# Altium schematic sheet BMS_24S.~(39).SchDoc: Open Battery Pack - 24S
size A3; Date: 26/03/2019; Author: Morgane Vallée - Samuel Lesueur; Revision: 1.0; SheetNumber: 3; SheetTotal: 5
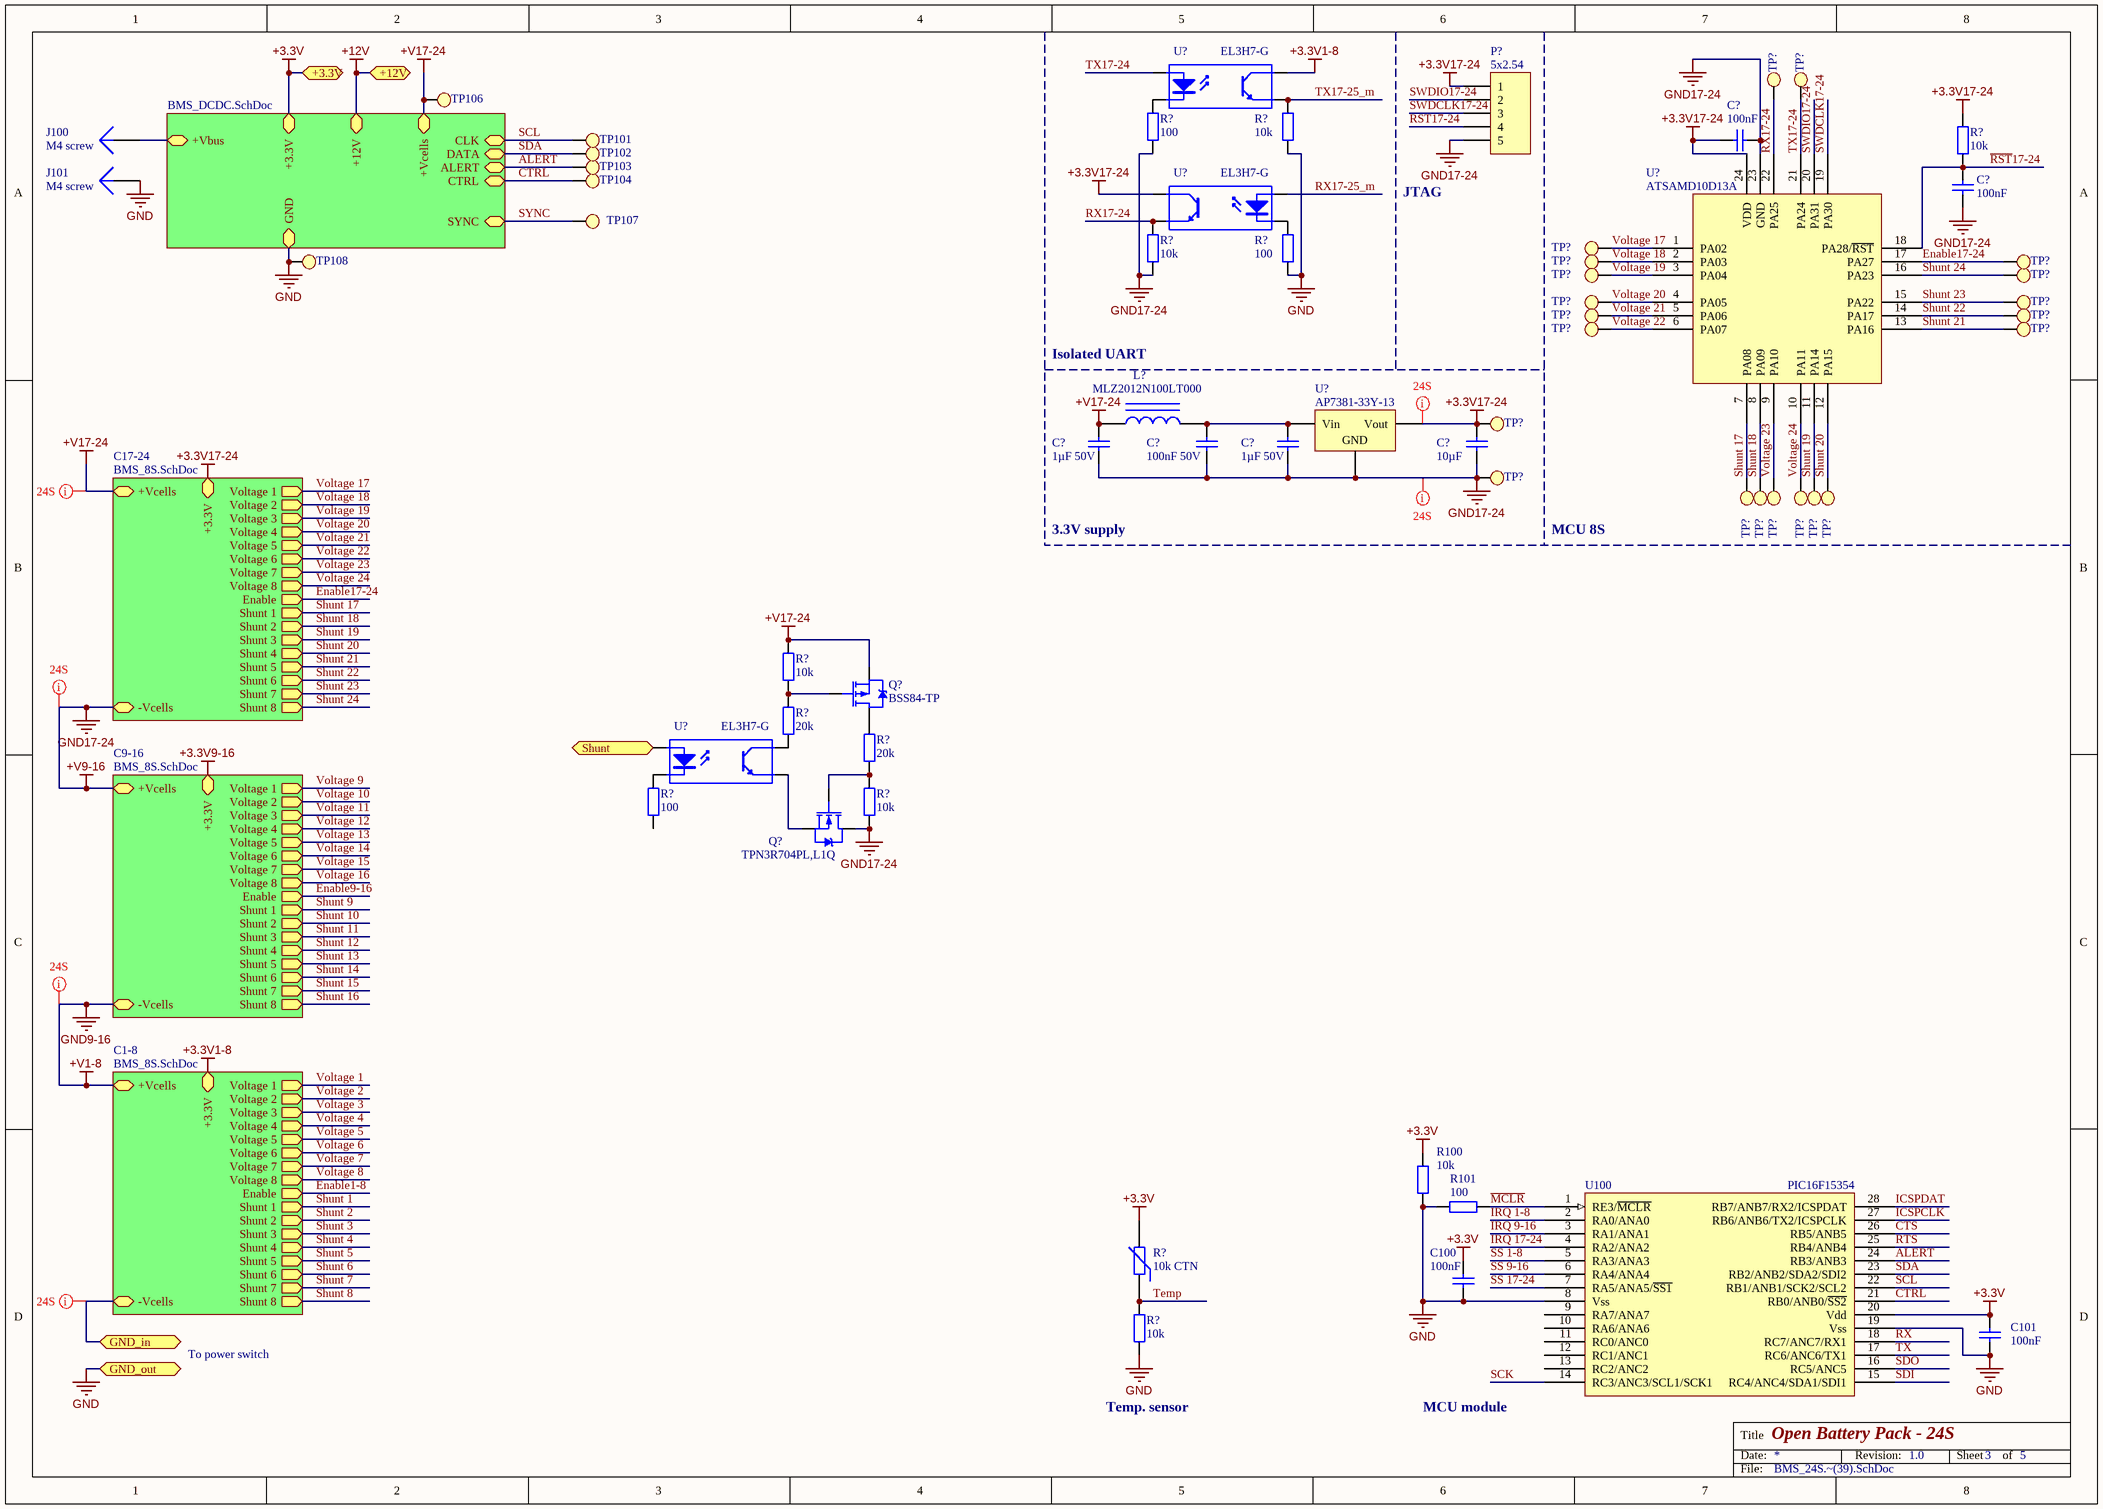
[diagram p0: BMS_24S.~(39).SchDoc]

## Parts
(Parts that share a designator on the sheet are numbered #1, #2 ... from top to bottom, then left to right.)
C100  100nF  [C0603]
C101  100nF  [C0603]
C?#1  100nF  [C0603]
C?#2  100nF  [C0603]
C?#3  1µF 50V  [C0805]
C?#4  100nF 50V  [C0603]
C?#5  1µF 50V  [C0805]
C?#6  10µF  [C0603]
J100  M4 screw  [HOLE_4]
J101  M4 screw  [HOLE_4]
L?  MLZ2012N100LT000  [FER 0805/2012]
P?  5x2.54  [HDR1X5]
Q?#1  BSS84-TP  [DIODES SOT-23-3]
Q?#2  TPN3R704PL,L1Q  [DIODES SOT-23-3]
R100  10k  [R0603]
R101  100  [R0603]
R?#1  10k  [R0603]
R?#2  100  [R0603]
R?#3  10k  [R0603]
R?#4  100  [R0603]
R?#5  10k  [R0603]
R?#6  10k  [R0603]
R?#7  20k  [R0603]
R?#8  20k  [R0603]
R?#9  100  [R0603]
R?#10  10k  [R0603]
R?#11  10k CTN  [NTC 0402/1005]
R?#12  10k  [R0603]
TP101  Test Point  [Test Point]  (value not drawn)
TP102  Test Point  [Test Point]  (value not drawn)
TP103  Test Point  [Test Point]  (value not drawn)
TP104  Test Point  [Test Point]  (value not drawn)
TP106  Test Point  [Test Point]  (value not drawn)
TP107  Test Point  [Test Point]  (value not drawn)
TP108  Test Point  [Test Point]  (value not drawn)
TP?#1  Test Point  [Test Point]  (value not drawn)
TP?#2  Test Point  [Test Point]  (value not drawn)
TP?#3  Test Point  [Test Point]  (value not drawn)
TP?#4  Test Point  [Test Point]  (value not drawn)
TP?#5  Test Point  [Test Point]  (value not drawn)
TP?#6  Test Point  [Test Point]  (value not drawn)
TP?#7  Test Point  [Test Point]  (value not drawn)
TP?#8  Test Point  [Test Point]  (value not drawn)
TP?#9  Test Point  [Test Point]  (value not drawn)
TP?#10  Test Point  [Test Point]  (value not drawn)
TP?#11  Test Point  [Test Point]  (value not drawn)
TP?#12  Test Point  [Test Point]  (value not drawn)
TP?#13  Test Point  [Test Point]  (value not drawn)
TP?#14  Test Point  [Test Point]  (value not drawn)
TP?#15  Test Point  [Test Point]  (value not drawn)
TP?#16  Test Point  [Test Point]  (value not drawn)
TP?#17  Test Point  [Test Point]  (value not drawn)
TP?#18  Test Point  [Test Point]  (value not drawn)
TP?#19  Test Point  [Test Point]  (value not drawn)
TP?#20  Test Point  [Test Point]  (value not drawn)
TP?#21  Test Point  [Test Point]  (value not drawn)
U100  PIC16F15354  [SSOP_28]
U?#1  EL3H7-G  [OPTO_EL3H7-G]
U?#2  EL3H7-G  [OPTO_EL3H7-G]
U?#3  ATSAMD10D13A  [SMSC QFN-24 4x4MM]
U?#4  AP7381-33Y-13  [ST SOIC-8N]
U?#5  EL3H7-G  [OPTO_EL3H7-G]

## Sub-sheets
C1-8 = BMS_8S.SchDoc: Voltage 6 (out), Shunt 2 (out), Shunt 7 (out), Shunt 6 (out), Voltage 3 (out), Voltage 5 (out), Shunt 8 (out), Voltage 8 (out), Voltage 7 (out), +3.3V, Voltage 2 (out), Shunt 4 (out), Shunt 3 (out), Shunt 5 (out), Voltage 4 (out), -Vcells, +Vcells, Shunt 1 (out), Voltage 1 (out), Enable (out)
C9-16 = BMS_8S.SchDoc: Voltage 6 (out), Shunt 2 (out), Shunt 7 (out), Shunt 6 (out), Voltage 3 (out), Voltage 5 (out), Shunt 8 (out), Voltage 8 (out), Voltage 7 (out), +3.3V, Voltage 2 (out), Shunt 4 (out), Shunt 3 (out), Shunt 5 (out), Voltage 4 (out), -Vcells, +Vcells, Shunt 1 (out), Voltage 1 (out), Enable (out)
C17-24 = BMS_8S.SchDoc: Voltage 6 (out), Shunt 2 (out), Shunt 7 (out), Shunt 6 (out), Voltage 3 (out), Voltage 5 (out), Shunt 8 (out), Voltage 8 (out), Voltage 7 (out), +3.3V, Voltage 2 (out), Shunt 4 (out), Shunt 3 (out), Shunt 5 (out), Voltage 4 (out), -Vcells, +Vcells, Shunt 1 (out), Voltage 1 (out), Enable (out)
? = BMS_DCDC.SchDoc: CTRL (bidir), SYNC (bidir), CLK (bidir), DATA (bidir), ALERT (bidir), GND, +3.3V, +Vbus, +Vcells, +12V

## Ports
+3.3V, +12V, GND_in, GND_out, Shunt (in)

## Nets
+3.3V: C100.2 C101.2 R100.2 R?#11.2 U100.20(Vdd) ; port +3.3V, sheet /+3.3V
+3.3V1-8: U?#1.4(C) ; sheet C1-8/+3.3V
+3.3V17-24: C?#1.2 C?#6.1 P?.1 R?#3.2 TP?#14.1 U?#2.4(C) U?#3.24(VDD) U?#4.3(Vout) ; sheet C17-24/+3.3V
+12V: port +12V, sheet /+12V
+V1-8: sheet C1-8/+Vcells, sheet C9-16/-Vcells  [also labelled GND9-16]
+V9-16: C?#1.1 C?#2.1 C?#3.2 C?#4.2 C?#5.2 C?#6.2 P?.5 Q?#2.3(D) R?#2.1 R?#5.1 R?#10.1 TP?#15.1 U?#3.23(GND) U?#4.2(GND) ; sheet C9-16/+Vcells, sheet C17-24/-Vcells  [also labelled GND17-24]
+V17-24: C?#3.1 L?.1 Q?#1.2(S) R?#6.2 TP106.1 ; sheet /+Vcells, sheet C17-24/+Vcells
GND: C100.1 C101.1 J101.1 R100.1 R101.2 R?#1.2 R?#4.2 R?#12.2 TP108.1 U100.8(Vss) U100.19(Vss) ; port GND_out, sheet /GND
ALERT: TP103.1 U100.24(RB3/ANB3) ; sheet /ALERT
CTRL: TP104.1 U100.21(RB0/ANB0/~{SS2}) ; sheet /CTRL
CTS: U100.26(RB5/ANB5)
Enable17-24: TP?#5.1 U?#3.17(PA27) ; sheet C17-24/Enable
GND_in: port GND_in, sheet C1-8/-Vcells
ICSPCLK: U100.27(RB6/ANB6/TX2/ICSPCLK)
ICSPDAT: U100.28(RB7/ANB7/RX2/ICSPDAT)
IRQ 1-8: U100.2(RA0/ANA0)
IRQ 9-16: U100.3(RA1/ANA1)
IRQ 17-24: U100.4(RA2/ANA2)
~{MCLR}: R101.1 U100.1(RE3/~{MCLR})
~{RST}17-24: C?#2.2 P?.4 R?#3.1 U?#3.18(PA28/~{RST})
RTS: U100.25(RB4/ANB4)
RX: U100.18(RC7/ANC7/RX1)
RX17-24: R?#5.2 TP?#1.1 U?#2.3(E) U?#3.22(PA25)
RX17-25_m: U?#2.1(A)
~{SS} 1-8: U100.5(RA3/ANA3)
~{SS} 9-16: U100.6(RA4/ANA4)
~{SS} 17-24: U100.7(RA5/ANA5/~{SS1})
SCK: U100.14(RC3/ANC3/SCL1/SCK1)
SCL: TP101.1 U100.22(RB1/ANB1/SCK2/SCL2) ; sheet /CLK
SDA: TP102.1 U100.23(RB2/ANB2/SDA2/SDI2) ; sheet /DATA
SDI: U100.15(RC4/ANC4/SDA1/SDI1)
SDO: U100.16(RC5/ANC5)
Shunt: U?#5.1(A) ; port Shunt
Shunt 17: TP?#16.1 U?#3.7(PA08) ; sheet C17-24/Shunt 1
Shunt 18: TP?#17.1 U?#3.8(PA09) ; sheet C17-24/Shunt 2
Shunt 19: TP?#20.1 U?#3.11(PA14) ; sheet C17-24/Shunt 3
Shunt 20: TP?#21.1 U?#3.12(PA15) ; sheet C17-24/Shunt 4
Shunt 21: TP?#13.1 U?#3.13(PA16) ; sheet C17-24/Shunt 5
Shunt 22: TP?#11.1 U?#3.14(PA17) ; sheet C17-24/Shunt 6
Shunt 23: TP?#9.1 U?#3.15(PA22) ; sheet C17-24/Shunt 7
Shunt 24: TP?#7.1 U?#3.16(PA23) ; sheet C17-24/Shunt 8
SWDCLK17-24: P?.3 U?#3.19(PA30)
SWDIO17-24: P?.2 U?#3.20(PA31)
SYNC: TP107.1 ; sheet /SYNC
Temp: R?#11.1 R?#12.1
TX: U100.17(RC6/ANC6/TX1)
TX17-24: TP?#2.1 U?#1.1(A) U?#3.21(PA24)
TX17-25_m: R?#1.1 U?#1.3(E)
Voltage 17: TP?#3.1 U?#3.1(PA02) ; sheet C17-24/Voltage 1
Voltage 18: TP?#4.1 U?#3.2(PA03) ; sheet C17-24/Voltage 2
Voltage 19: TP?#6.1 U?#3.3(PA04) ; sheet C17-24/Voltage 3
Voltage 20: TP?#8.1 U?#3.4(PA05) ; sheet C17-24/Voltage 4
Voltage 21: TP?#10.1 U?#3.5(PA06) ; sheet C17-24/Voltage 5
Voltage 22: TP?#12.1 U?#3.6(PA07) ; sheet C17-24/Voltage 6
Voltage 23: TP?#18.1 U?#3.9(PA10) ; sheet C17-24/Voltage 7
Voltage 24: TP?#19.1 U?#3.10(PA11) ; sheet C17-24/Voltage 8
NetC?#4_1: C?#4.1 C?#5.1 L?.2 U?#4.1(Vin)
NetJ100_1: J100.1 ; sheet /+Vbus
NetQ?#1_1: Q?#1.1(G) R?#6.1 R?#7.2
NetQ?#1_3: Q?#1.3(D) R?#8.2
NetQ?#2_1: Q?#2.1(G) R?#8.1 R?#10.2
NetQ?#2_2: Q?#2.2(S) U?#5.3(E)
NetR?#2_2: R?#2.2 U?#1.2(K)
NetR?#4_1: R?#4.1 U?#2.2(K)
NetR?#7_1: R?#7.1 U?#5.4(C)
NetR?#9_2: R?#9.2 U?#5.2(K)

Not connected (* = marked no-connect by the designer): R?#9 1; U100 9(RA7/ANA7) 10(RA6/ANA6) 11(RC0/ANC0) 12(RC1/ANC1) 13(RC2/ANC2)

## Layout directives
net class 24S: +3.3V17-24, +V1-8, +V9-16, +V17-24, GND_in

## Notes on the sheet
- JTAG
- Isolated UART
- 3.3V supply
- MCU 8S
- To power switch
- Temp. sensor
- MCU module

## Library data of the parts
C100 C101 C?#1-C?#6 = Cap: Capacitor
J100 J101 = Plug
L? = Inductor Iron: Magnetic-Core Inductor
P? = Header 5: Header, 5-Pin
Q?#1 = MOSFET_P
Q?#2 = MOSFET_N
R100 R101 R?#1-R?#10 R?#12 = Res2: Resistor
R?#11 = Res Varistor: Varistor (Voltage-Sensitive Resistor)
U?#1 U?#2 U?#5 = Optoisolator1: 4-Pin Phototransistor Optocoupler
U?#4 = Volt Reg: Voltage Regulator; pin to pad: 1>8 2>2+3+6+7 3>1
